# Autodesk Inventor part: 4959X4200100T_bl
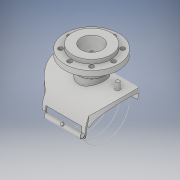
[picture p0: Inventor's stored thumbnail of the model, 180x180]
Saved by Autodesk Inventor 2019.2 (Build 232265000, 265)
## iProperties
Created: 2020-06
Part Number: 4959X4200100T_bl
Material: Generic
Description: Plasson Flanged Branch Saddle 200x100
Document SubType Name: Modeling
Designer: KIM
Density: 1 g/cm^3
Appearance: Default
Author: KIM
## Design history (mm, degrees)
derived "4959X4.ipt"
feature "Solid1::4959X4.ipt" dims "ScaleForDerivedMember" = 10
feature "Solid2::4959X4.ipt" dims "ScaleForDerivedMember" = 10
tag "TaggingFeature1"
body "Solid1"
body "Solid2"
other parameters: "d0" = 295 [user parameter], "d7" = 87 [user parameter], "d10" = 0.5 [user parameter], "d11" = 1 [user parameter], "d13" = 16 [user parameter], "d14" = 8 [user parameter], "d16" = 10 deg [user parameter], "d17" = 10 deg [user parameter], "d19" = 0 [user parameter], "d23" = 0 [user parameter], "d26" = 0 [user parameter], "d27" = 177 [user parameter], "d28" = 0 [user parameter], "d29" = 147.5 [user parameter], "d30" = 0 [user parameter], "d31" = 1 [user parameter], "d32" = 1 [user parameter], "d33" = 19.2 [user parameter], "d34" = 9.6 [user parameter], "d35" = 45 deg [user parameter], "d36" = 147.5 [user parameter], "d37" = 0 [user parameter], "d38" = 5 [user parameter], "d39" = 85 deg [user parameter], "d41" = 16 [user parameter], "d42" = 107.27273 [user parameter], "d49" = 3 [user parameter], "d50" = 6 [user parameter], "d51" = 5 [user parameter], "d54" = 0 [user parameter], "d57" = 35 deg [user parameter], "d60" = 18.4375 [user parameter], "d61" = 1 [user parameter], "d62" = 90 deg [user parameter], "d63" = 2 [user parameter], "d64" = 0 [user parameter], "d65" = 0 [user parameter], "d68" = 36.875 [user parameter], "d70" = 0.57711 [user parameter], "d71" = 10 deg [user parameter], "d73" = 5.25 [user parameter], "d75" = 22 [user parameter], "d77" = 89.25 [user parameter], "d78" = 105 [user parameter], "d79" = 158 [user parameter], "d80" = 1 [user parameter], "d81" = 104.4 [user parameter], "d82" = 121.8 [user parameter], "d83" = 1 [user parameter], "d84" = 16.5 [user parameter], "d87" = 18 [user parameter], "d95" = 360 deg [user parameter], "d_h" = 158 [user parameter], "B" = 277 [user parameter], "L" = 295 [user parameter], "LS" = 105 [user parameter], "Dt" = 16 [user parameter], "di" = 87 [user parameter], "s_" = 18 [user parameter], "t" = 22 [user parameter], "d72" = 15 [user parameter]
